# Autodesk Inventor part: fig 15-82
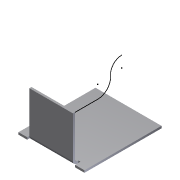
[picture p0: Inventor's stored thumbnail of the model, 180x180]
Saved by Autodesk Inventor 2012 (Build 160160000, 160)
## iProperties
Shininess: 77.0
Angle Display Precision: 2
Document Length Units: 11269
Document Angle Units: 11279
Document Time Units: 11290
Document Mass Units: 11283
Document Length Units Precision: 3
Document Angle Units Precision: 2
Compacted: True
Created: 2002-04
Part Number: fig 15-82
Document SubType Name: Sheet Metal
Density: 1 g/cm^3
Sheet Metal Rule: Default
Material: Default
Density: 0.0
Volumn: 0.0
Area: 0.0
PropertySet Name: Model Information
Control State: 0
Master: False
Checked Out: False
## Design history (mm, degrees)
node "Face1"
  sketch "Sketch1"
    geometry: L1 (-24.824, 17.882)-(5.529, 17.882); L2 (5.529, 17.882)-(5.529, -17.529); L3 (5.529, -17.529)-(-24.824, -17.529); L4 (-24.824, -17.529)-(-24.824, 17.882)
    constraints: 8 end point, 2 parallel, 1 horizontal, 1 perpendicular
node "Flange1"
sketch "Sketch5"
  geometry: L1 (0, 1)-(0, 11.431); A1 r 5.855 centre (-5.855, 11.431) between (0, 11.431) and (-6.422, 17.259); A2 r 5.142 centre (-6.92, 22.376) between (-12.062, 22.382) and (-6.422, 17.259)
  constraints: 4 point on circle, 2 centre point, 2 end point, 2 tangent
body "Solid1"
face "Plate1" dims "Thickness" = 1
sketch "Sketch3"
  geometry: L1 (25.353, 0)-(5.353, 0); L2 (5.353, 0)-(5.353, 20); L3 (5.353, 20)-(25.353, 20); L4 (25.353, 20)-(25.353, 0)
  constraints: 8 end point
face "Plate3" dims "d5" = 20, "d6" = 90 deg, "d7" = 1 (= BendRadius), "d11" = 5, "d12" = 20, "Thickness" = 1, "MinimumRemnant" = 2 (= 2 x Thickness), "BendReliefWidth" = 1 (= Thickness)
bend "Bend2" dims "d5" = 20, "d6" = 90 deg, "d7" = 1 (= BendRadius), "d21" = 1 (= BendReliefWidth), "d22" = 0.5 (= BendReliefDepth), "d23" = 2 (= MinimumRemnant), "SeamGap" = 0.01, "Thickness" = 1, "MinimumRemnant" = 2 (= 2 x Thickness), "BendReliefWidth" = 1 (= Thickness), "TransitionRadius" = 1 (= BendRadius)
other parameters: "BendRadius" = 1 (= Thickness), "BendReliefDepth" = 0.5 (= 0.5 x Thickness), "CornerReliefSize" = 4 (= 4 x Thickness), "d0" = 1 (= BendRadius), "d4" = 1 (= BendRadius), "JacobiRadiusSize" = 1 (= Thickness), "GapSize" = 1 (= Thickness)
